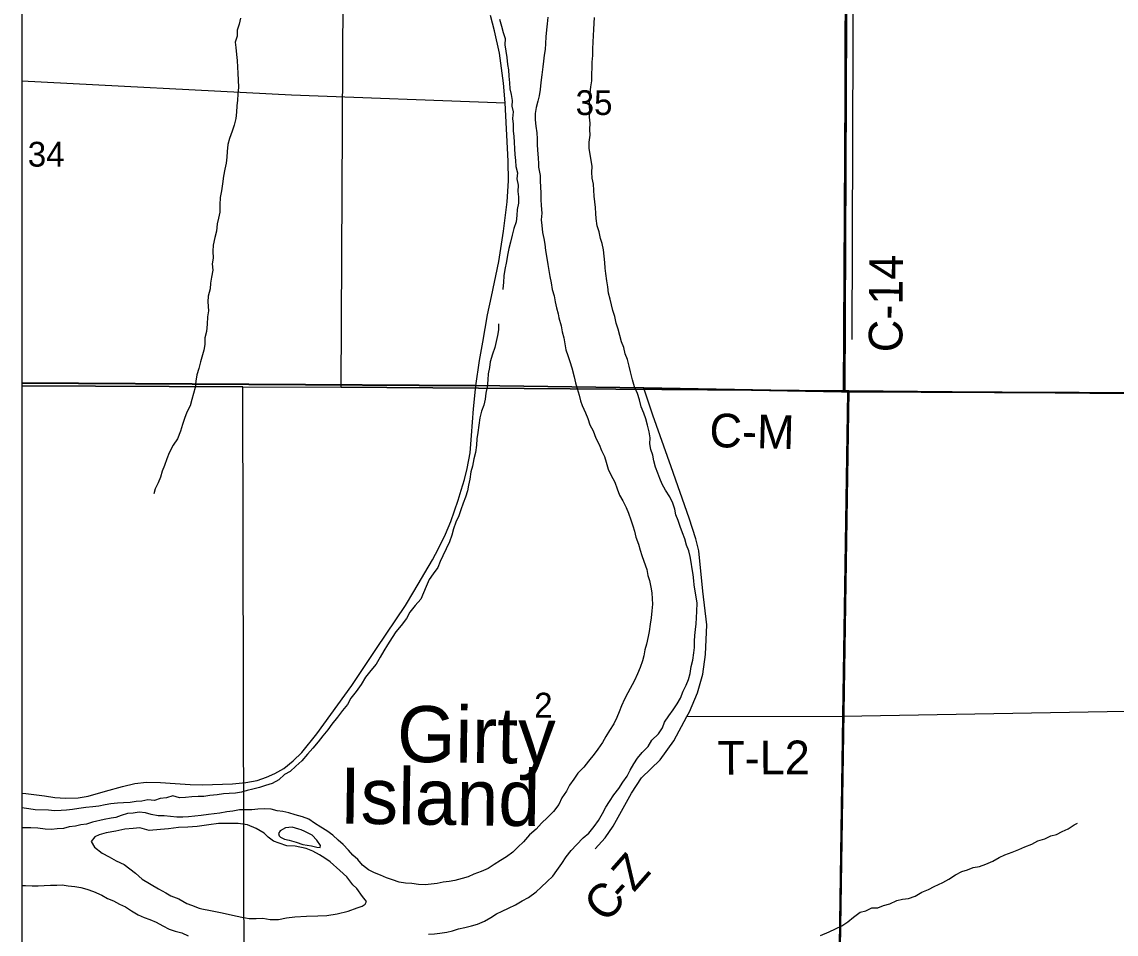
# Model space of a CAD drawing. Extents: x -6.2 to 37.4, y 0.2 to 22.2.
# Drawn here: x 1.681 to 2.605, y 14.922 to 15.692 of the extents above; entities that cross this region are included whole.
import ezdxf

# ---------------------------------------------------------------- set-up
doc = ezdxf.new("R2010")
doc.units = 0
for name, color, linetype in [('GM_X_County_Road', 7, 'Continuous'), ('GM_X_County_Road_Text', 7, 'Continuous'), ('GM_X_Major_River', 7, 'Continuous'), ('GM_X_Major_River_Text', 7, 'Continuous'), ('GM_X_Minor_River', 7, 'Continuous'), ('GM_X_Rail_Line', 7, 'Continuous'), ('GM_X_Section', 7, 'Continuous'), ('GM_X_Section_Text', 7, 'Continuous'), ('GM_X_Township_Road', 7, 'Continuous'), ('GM_X_Township_Road_Text', 7, 'Continuous'), ('GM_X_US_Shield', 7, 'Continuous'), ('SH_Cut_Line', 7, 'Continuous'), ('SH_Data', 7, 'Continuous')]:
    doc.layers.add(name, color=color, linetype=linetype)

msp = doc.modelspace()

# ---------------------------------------------------------------- linework, layer by layer
at = {"layer": 'GM_X_County_Road'}
for p, q in [((2.2059, 15.38289), (2.37282, 15.37973)), ((2.37282, 15.37973), (2.3744, 15.3797)), ((2.3744, 15.3797), (2.37821, 15.37963)), ((2.37821, 15.37963), (2.76889, 15.37789))]:
    msp.add_line(p, q, dxfattribs=at)
for points in [[(2.3744, 15.3797), (2.37573, 15.63221), (2.37619, 15.75431), (2.37666, 15.88116), (2.38391, 16.32379), (2.3895, 16.61161)], [(1.68086, 15.04078), (1.68433, 15.0405), (1.69989, 15.03854), (1.70873, 15.03727), (1.71756, 15.03678), (1.72844, 15.0371), (1.73669, 15.03833), (1.75134, 15.04253), (1.76581, 15.04659), (1.77609, 15.04898), (1.78597, 15.0501), (1.79782, 15.04996), (1.81015, 15.04919), (1.82283, 15.04814), (1.83322, 15.04786), (1.85852, 15.0487), (1.86995, 15.04982), (1.87941, 15.05157), (1.88726, 15.05439), (1.8945, 15.05762), (1.90191, 15.06174), (1.90983, 15.06812), (1.91705, 15.07513), (1.92981, 15.09111), (1.95939, 15.13183), (1.98024, 15.16291), (2.00467, 15.19926), (2.01184, 15.21123), (2.02751, 15.23774), (2.0325, 15.24735), (2.03853, 15.25941), (2.04301, 15.2702), (2.04918, 15.28815), (2.05177, 15.29663), (2.05451, 15.30567), (2.05689, 15.31506), (2.0592, 15.32824), (2.06054, 15.34275), (2.06209, 15.36536), (2.0642, 15.38463), (2.06723, 15.40608), (2.06989, 15.4217), (2.07399, 15.44463), (2.07722, 15.46006), (2.08349, 15.48957), (2.08756, 15.51522), (2.09061, 15.54017), (2.09162, 15.5578), (2.09134, 15.57428), (2.08889, 15.62362), (2.08742, 15.64013), (2.08395, 15.66565), (2.07985, 15.68454), (2.07645, 15.69747)], [(2.24231, 15.10557), (2.24455, 15.10965), (2.25109, 15.12557), (2.25574, 15.1415), (2.25791, 15.15782), (2.259, 15.18307), (2.25573, 15.21138), (2.2523, 15.24557), (2.24988, 15.25546), (2.24408, 15.27295), (2.22892, 15.31632), (2.21338, 15.35988), (2.2059, 15.38289)], [(2.37011, 14.85446), (2.37392, 15.10601), (2.37821, 15.37963)], [(2.16484, 14.99391), (2.16494, 14.99402), (2.1733, 15.00327), (2.18001, 15.01311), (2.19535, 15.04095), (2.20397, 15.05382), (2.21982, 15.06913), (2.23112, 15.08522), (2.24231, 15.10557)]]:
    msp.add_lwpolyline(points, dxfattribs=at)
at = {"layer": 'GM_X_Major_River'}
for p, q in [((1.91663, 15.00983), (1.91456, 15.01062)), ((1.80236, 14.95691), (1.80668, 14.95438))]:
    msp.add_line(p, q, dxfattribs=at)
for points in [[(2.12491, 15.69584), (2.12443, 15.69034), (2.12378, 15.68522), (2.1233, 15.67935), (2.12283, 15.67385), (2.12255, 15.66873), (2.12172, 15.66388), (2.12106, 15.65888), (2.12059, 15.65395), (2.11972, 15.64732), (2.11904, 15.64088)], [(2.17228, 15.4943), (2.17179, 15.49943), (2.17068, 15.50494), (2.16931, 15.50915), (2.16808, 15.51486), (2.16664, 15.51982), (2.16575, 15.526), (2.16531, 15.53028), (2.16501, 15.53522), (2.16452, 15.53997), (2.16404, 15.54491), (2.16356, 15.55005), (2.16345, 15.55498), (2.1624, 15.56012), (2.16211, 15.56506), (2.16219, 15.57), (2.16152, 15.57513), (2.16066, 15.58008), (2.1598, 15.58541), (2.15989, 15.59053), (2.16056, 15.59641), (2.16045, 15.60115), (2.16073, 15.60646), (2.16005, 15.61141), (2.16033, 15.61634), (2.16003, 15.62128), (2.15993, 15.62622), (2.16059, 15.63171), (2.16125, 15.63701), (2.1619, 15.64213), (2.162, 15.64801), (2.16228, 15.65313), (2.16218, 15.65807), (2.16284, 15.66356), (2.16293, 15.66926), (2.16322, 15.67495), (2.16331, 15.68045), (2.16378, 15.68557), (2.16406, 15.69088), (2.16414, 15.69562)], [(2.11904, 15.64088), (2.11837, 15.63501), (2.11752, 15.62951), (2.1164, 15.62497), (2.11508, 15.61968), (2.11424, 15.61457), (2.11428, 15.60925), (2.11481, 15.60393), (2.11548, 15.59842), (2.11577, 15.59329), (2.11595, 15.58835), (2.11617, 15.58375), (2.11663, 15.57733), (2.11693, 15.5722), (2.11703, 15.56932), (2.11827, 15.56231), (2.11838, 15.55718), (2.11865, 15.55307), (2.11896, 15.54711), (2.11906, 15.54199), (2.11936, 15.53705), (2.11982, 15.53059), (2.11934, 15.5249), (2.11983, 15.51996), (2.1203, 15.51426), (2.12135, 15.50912), (2.12221, 15.50436), (2.12288, 15.49903), (2.1241, 15.49256), (2.12477, 15.48724), (2.12563, 15.4821), (2.12649, 15.47715), (2.12772, 15.47182), (2.12858, 15.46611), (2.13019, 15.46077), (2.13105, 15.45563), (2.13229, 15.45049), (2.13372, 15.44553), (2.13422, 15.44211), (2.13601, 15.43544), (2.13687, 15.4303), (2.1383, 15.42515), (2.14003, 15.41526), (2.14165, 15.41049), (2.14346, 15.40515), (2.14507, 15.39981), (2.14703, 15.39238), (2.14827, 15.38742), (2.14971, 15.38247), (2.15132, 15.37694), (2.15238, 15.37218), (2.15384, 15.36803), (2.15656, 15.36205), (2.15875, 15.35708), (2.16037, 15.35193), (2.16313, 15.34677), (2.16549, 15.34066), (2.16824, 15.3353), (2.17024, 15.33015), (2.17263, 15.32501), (2.17424, 15.32041), (2.17584, 15.3145), (2.17804, 15.30972), (2.18141, 15.30353), (2.18352, 15.29787), (2.18533, 15.29253), (2.18828, 15.28774), (2.19102, 15.282), (2.19303, 15.27723), (2.19502, 15.27169), (2.19666, 15.2665), (2.19788, 15.26197), (2.19913, 15.25702), (2.2013, 15.2511), (2.20273, 15.24595), (2.20411, 15.24154), (2.20593, 15.23684), (2.20833, 15.22973), (2.20938, 15.22459), (2.21075, 15.22049), (2.21186, 15.21469), (2.21254, 15.20993), (2.21306, 15.20504), (2.21314, 15.20043), (2.21266, 15.19494), (2.21218, 15.18887), (2.21133, 15.18357), (2.21028, 15.17751), (2.20966, 15.17329), (2.2082, 15.16672), (2.20679, 15.16181), (2.20595, 15.15689), (2.20486, 15.15254), (2.20278, 15.14704), (2.20057, 15.1416), (2.19801, 15.13613), (2.19252, 15.12559), (2.18959, 15.12013), (2.18703, 15.11466), (2.18505, 15.10957), (2.18307, 15.10466)], [(2.13233, 14.97562), (2.1366, 14.98163), (2.1403, 14.98707), (2.14456, 14.99251), (2.14901, 14.99738), (2.1546, 15.00318), (2.15941, 15.00728), (2.16387, 15.01291), (2.16755, 15.01779), (2.17088, 15.02381), (2.17381, 15.02908), (2.17693, 15.03396), (2.18062, 15.03941), (2.1847, 15.04485), (2.1882, 15.0503), (2.1917, 15.05519), (2.19425, 15.06046), (2.19737, 15.06554), (2.20068, 15.07042), (2.20455, 15.0753), (2.20957, 15.08035), (2.21269, 15.08561), (2.21828, 15.09103), (2.22159, 15.09592), (2.22338, 15.10083), (2.22688, 15.10628), (2.23076, 15.11115), (2.23407, 15.11622), (2.2368, 15.12112), (2.23918, 15.12697), (2.24173, 15.13205), (2.24352, 15.13696), (2.24493, 15.14187), (2.24579, 15.14793), (2.2474, 15.15322), (2.24805, 15.15931), (2.24853, 15.16383), (2.24868, 15.16914), (2.24908, 15.17388), (2.24955, 15.17919), (2.24995, 15.1839), (2.25028, 15.18886), (2.25076, 15.19455), (2.25096, 15.20116), (2.24999, 15.20651), (2.24935, 15.21153), (2.24849, 15.21666), (2.24806, 15.22019), (2.2475, 15.22553), (2.24677, 15.23024), (2.24577, 15.23581), (2.24491, 15.24076), (2.24386, 15.24552), (2.24204, 15.25029), (2.24043, 15.25563), (2.23862, 15.26059), (2.23643, 15.26594), (2.235, 15.27109), (2.233, 15.27586), (2.23194, 15.28062), (2.23033, 15.28577), (2.22776, 15.29094), (2.22407, 15.29669), (2.22131, 15.30166), (2.21931, 15.30644), (2.21785, 15.31104), (2.21568, 15.31617), (2.21425, 15.32132), (2.21339, 15.32627), (2.21176, 15.33104), (2.21109, 15.33579), (2.21117, 15.34092), (2.21031, 15.34605), (2.20889, 15.35158), (2.20766, 15.35691), (2.20584, 15.36169), (2.20366, 15.36703), (2.20224, 15.37294), (2.20044, 15.37828), (2.19788, 15.38401), (2.19646, 15.38973), (2.19468, 15.39659), (2.19344, 15.40135), (2.19202, 15.40688), (2.1902, 15.41184), (2.18897, 15.41699), (2.18715, 15.42195), (2.18554, 15.4271), (2.1843, 15.43262), (2.1825, 15.43777), (2.18147, 15.44321), (2.17983, 15.44825), (2.17859, 15.45321), (2.17734, 15.45797), (2.1761, 15.46292), (2.17543, 15.46825), (2.17476, 15.47338), (2.17375, 15.47945), (2.17324, 15.48404), (2.17294, 15.48898), (2.17228, 15.4943)], [(2.18307, 15.10466), (2.1807, 15.09938), (2.17701, 15.09394), (2.17388, 15.08867), (2.17095, 15.08359), (2.16707, 15.07795), (2.16398, 15.07373), (2.15931, 15.06801), (2.15525, 15.06295), (2.1503, 15.05779), (2.14673, 15.05264), (2.14323, 15.04757), (2.14049, 15.04268), (2.13679, 15.03685), (2.13423, 15.03139), (2.12958, 15.02538), (2.12457, 15.02033), (2.11956, 15.01567), (2.11492, 15.01061), (2.10934, 15.00576), (2.10431, 14.99996), (2.09967, 14.99533), (2.09525, 14.99117), (2.09006, 14.9873), (2.0849, 14.98412), (2.07953, 14.98078), (2.07436, 14.97745), (2.06863, 14.97488), (2.06252, 14.9725), (2.05755, 14.9703), (2.05241, 14.96886), (2.04632, 14.96725), (2.04156, 14.96637), (2.03662, 14.96568), (2.03149, 14.96462), (2.02631, 14.96401), (2.02142, 14.96345), (2.01574, 14.96391), (2.01007, 14.96457), (2.00457, 14.96484), (1.99947, 14.96568), (1.99382, 14.96785), (1.98873, 14.96945), (1.98346, 14.97162), (1.97857, 14.97378), (1.97349, 14.97632), (1.96844, 14.98), (1.96454, 14.985), (1.96029, 14.9885), (1.95652, 14.99271), (1.95206, 14.99752), (1.94798, 15.00132), (1.94328, 15.00544), (1.93842, 15.00912), (1.93316, 15.01223), (1.92791, 15.01554), (1.92307, 15.01883), (1.91777, 15.02101), (1.91154, 15.02262), (1.90626, 15.02422), (1.90116, 15.02543), (1.89624, 15.02589), (1.89134, 15.02729), (1.88547, 15.02757), (1.87996, 15.02727), (1.87503, 15.02697), (1.86953, 15.02686), (1.8646, 15.02675), (1.85908, 15.02569), (1.85377, 15.02502), (1.84806, 15.02415), (1.84331, 15.02347), (1.83838, 15.02297), (1.83229, 15.02212), (1.82698, 15.02144), (1.82151, 15.0209), (1.81673, 15.02065), (1.8118, 15.02072), (1.80631, 15.02118), (1.80101, 15.02183), (1.7959, 15.02191), (1.79003, 15.02276), (1.78513, 15.02435), (1.77983, 15.02481), (1.77489, 15.02413), (1.77015, 15.02382), (1.76475, 15.02204), (1.76004, 15.02037), (1.7562, 15.01969), (1.75035, 15.01881), (1.74045, 15.0163), (1.73549, 15.01486), (1.73074, 15.01417), (1.72599, 15.01311), (1.72067, 15.01243), (1.7159, 15.01098), (1.71066, 15.01068), (1.70584, 15.01019), (1.70054, 15.01065), (1.6943, 15.01131), (1.68843, 15.01178)], [(1.68843, 15.01178), (1.68351, 15.01152), (1.68086, 15.01174)], [(1.80668, 14.95438), (1.81346, 14.95162), (1.82003, 14.94791), (1.82398, 14.94633), (1.83057, 14.94377), (1.83284, 14.94316), (1.84021, 14.94191), (1.84984, 14.93987), (1.85853, 14.93784), (1.86646, 14.9362), (1.8727, 14.93497), (1.87857, 14.93507), (1.88427, 14.93536), (1.8905, 14.93431), (1.89752, 14.9344), (1.90437, 14.93581), (1.91139, 14.93665), (1.92126, 14.93707), (1.93074, 14.9375), (1.93833, 14.93776), (1.94688, 14.93896), (1.9564, 14.94128), (1.96403, 14.9442), (1.96804, 14.94566), (1.97072, 14.94714), (1.9717, 14.9494), (1.96837, 14.95382), (1.96355, 14.96053), (1.96038, 14.96362), (1.95519, 14.97015), (1.94922, 14.97574), (1.94119, 14.98308), (1.9367, 14.98618), (1.932, 14.98891), (1.92656, 14.99184), (1.92072, 14.9942), (1.91146, 14.99605), (1.90465, 14.99654), (1.89805, 14.99872), (1.89334, 15.0005), (1.88885, 15.0038), (1.88531, 15.00727), (1.87874, 15.01097), (1.8714, 15.01431), (1.86346, 15.01538), (1.85625, 15.0153), (1.84677, 15.01525), (1.83861, 15.01424), (1.82872, 15.01287), (1.82094, 15.01223), (1.81317, 15.01197), (1.80461, 15.01077), (1.79797, 15.01011), (1.78829, 15.0095), (1.78056, 15.01171), (1.77467, 15.01104), (1.76765, 15.01057), (1.76022, 15.00879), (1.75205, 15.0074), (1.74614, 15.00578), (1.74251, 15.00413), (1.73941, 15), (1.74217, 14.99521), (1.74872, 14.99037), (1.75454, 14.98705), (1.76036, 14.98374), (1.76732, 14.98059), (1.77686, 14.97324), (1.78247, 14.96841), (1.79617, 14.96023), (1.80236, 14.95691)], [(1.91456, 15.01062), (1.9089, 15.01222), (1.90339, 15.01174), (1.8988, 15.00915), (1.89762, 15.00689), (1.89797, 15.00499), (1.89909, 15.00383), (1.90247, 15.00207), (1.90644, 15.00125), (1.91247, 14.99945), (1.91793, 14.99747), (1.92531, 14.99641), (1.92984, 14.9952), (1.93268, 14.99516), (1.9329, 14.99686), (1.92994, 15.00127), (1.92584, 15.00551), (1.91983, 15.00864), (1.91663, 15.00983)], [(2.02412, 14.92185), (2.02922, 14.92222), (2.0338, 14.92284), (2.0395, 14.9237), (2.04429, 14.9248), (2.04952, 14.9263), (2.05473, 14.92745), (2.06043, 14.92887), (2.06559, 14.93033), (2.07151, 14.93289), (2.07668, 14.93585), (2.08147, 14.93919), (2.08644, 14.9414), (2.0916, 14.94378), (2.09752, 14.94654), (2.10327, 14.95006), (2.10844, 14.95283), (2.11509, 14.95761), (2.11925, 14.96146), (2.12421, 14.96625), (2.12902, 14.97073), (2.13233, 14.97562)], [(1.68086, 14.963), (1.68399, 14.96308), (1.68968, 14.9628), (1.6946, 14.96272), (1.69973, 14.96303), (1.70504, 14.96333), (1.71026, 14.96322), (1.7149, 14.96355), (1.71988, 14.9628), (1.72568, 14.96206), (1.73059, 14.96123), (1.73569, 14.95982), (1.74134, 14.95803), (1.7483, 14.95488), (1.75318, 14.95196), (1.75827, 14.94999), (1.76315, 14.94726), (1.76842, 14.94509), (1.77348, 14.9416), (1.7791, 14.9381), (1.784, 14.93593), (1.7889, 14.93434), (1.79435, 14.93198), (1.7998, 14.92886), (1.80525, 14.92612), (1.81015, 14.92453), (1.81581, 14.92293), (1.82127, 14.92057)]]:
    msp.add_lwpolyline(points, dxfattribs=at)
at = {"layer": 'GM_X_Minor_River'}
for points in [[(2.27558, 15.76113), (2.38269, 15.7616), (2.38148, 15.42375)], [(1.86539, 15.69521), (1.86416, 15.68992), (1.86256, 15.685), (1.86248, 15.67988), (1.86088, 15.67497), (1.86155, 15.67021), (1.86202, 15.66432), (1.86251, 15.65938), (1.86298, 15.65368), (1.86327, 15.64874), (1.86355, 15.64266), (1.86383, 15.63677), (1.86316, 15.6309), (1.86288, 15.62597), (1.86242, 15.62104), (1.86214, 15.61573), (1.86148, 15.61043), (1.86006, 15.60475), (1.85827, 15.59965), (1.85626, 15.59342), (1.85485, 15.58851), (1.85418, 15.58263), (1.85391, 15.5777), (1.85326, 15.57278), (1.85222, 15.56767), (1.85099, 15.5618), (1.85012, 15.55536), (1.84926, 15.54949), (1.84822, 15.54381), (1.84792, 15.53755), (1.84801, 15.53148), (1.84697, 15.52637), (1.84575, 15.52145), (1.84527, 15.51539), (1.84385, 15.51009), (1.84222, 15.50348), (1.84213, 15.49835), (1.84241, 15.49265), (1.84138, 15.48774), (1.84205, 15.48241), (1.84081, 15.47635), (1.84016, 15.47143), (1.83988, 15.4665), (1.83807, 15.46045), (1.8378, 15.45571), (1.83843, 15.44792), (1.83759, 15.443), (1.83729, 15.43693), (1.83662, 15.43068), (1.83539, 15.42538), (1.83529, 15.41969), (1.83445, 15.41477), (1.83163, 15.40494), (1.83021, 15.39945), (1.8286, 15.39398)], [(2.08394, 15.69437), (2.08573, 15.68846), (2.08716, 15.68293), (2.08897, 15.67797), (2.08849, 15.67247), (2.09021, 15.66182), (2.09087, 15.65611), (2.09155, 15.65136), (2.09184, 15.64623), (2.0925, 15.64052), (2.09279, 15.63539), (2.09404, 15.63063), (2.09471, 15.62568)], [(2.09471, 15.62568), (2.09444, 15.62094), (2.09568, 15.61599), (2.09502, 15.61031), (2.0955, 15.60555), (2.0956, 15.60005), (2.09628, 15.59529), (2.09657, 15.59054), (2.09667, 15.58484), (2.09696, 15.57991), (2.09745, 15.57496), (2.09774, 15.57002), (2.09917, 15.56469), (2.0987, 15.55938), (2.09993, 15.55405), (2.09966, 15.54893), (2.10015, 15.54417), (2.10006, 15.53905), (2.09883, 15.53356), (2.09855, 15.52844), (2.09808, 15.52314), (2.09609, 15.51766), (2.09467, 15.51199), (2.09324, 15.50594), (2.09201, 15.50064), (2.09078, 15.49496), (2.08993, 15.48966), (2.08867, 15.48285), (2.08783, 15.47774), (2.08735, 15.47205), (2.08688, 15.46674), (2.08683, 15.46619)], [(2.0831, 15.43718), (2.08315, 15.43681), (2.08326, 15.43206), (2.08242, 15.42714), (2.0812, 15.42222), (2.08016, 15.41711), (2.07817, 15.41145), (2.07616, 15.40503), (2.07551, 15.4001), (2.07447, 15.3948), (2.0742, 15.38968), (2.07353, 15.384), (2.07249, 15.37851), (2.07183, 15.3734), (2.0708, 15.36848), (2.06882, 15.36338), (2.06759, 15.35771), (2.06672, 15.35146), (2.06567, 15.3454), (2.06501, 15.34009), (2.06473, 15.33459), (2.06368, 15.32854), (2.06225, 15.32305), (2.0612, 15.31699), (2.05979, 15.31208), (2.05893, 15.30602), (2.0579, 15.30091), (2.05706, 15.29599), (2.05545, 15.2907), (2.05347, 15.28579), (2.05147, 15.27994), (2.04968, 15.27503), (2.04713, 15.26957), (2.04532, 15.2639), (2.04372, 15.2588), (2.04172, 15.25295), (2.03916, 15.24729), (2.03622, 15.24126), (2.03386, 15.23636), (2.03188, 15.23146), (2.02818, 15.22601), (2.02469, 15.22113), (2.02213, 15.21547), (2.01976, 15.21001), (2.01758, 15.20454), (2.01294, 15.19929), (2.00849, 15.19367), (2.00555, 15.1884), (2.00109, 15.18239), (1.99664, 15.17714), (1.99353, 15.17226), (1.98963, 15.16605), (1.98651, 15.16117), (1.98339, 15.15571), (1.97987, 15.14988), (1.97542, 15.14444), (1.97097, 15.13882), (1.96726, 15.13261), (1.96299, 15.12679), (1.95853, 15.12097), (1.9556, 15.11589), (1.95153, 15.11064), (1.94726, 15.1052), (1.94261, 15.0992), (1.93912, 15.09432), (1.93486, 15.08926), (1.93098, 15.08419)], [(1.8286, 15.39398), (1.82775, 15.38867), (1.82728, 15.38337), (1.82568, 15.37827), (1.82446, 15.37316), (1.82304, 15.36787), (1.8201, 15.3626), (1.81812, 15.35712), (1.81651, 15.35202), (1.8149, 15.34635), (1.81233, 15.34013), (1.80844, 15.33468), (1.8053, 15.32828), (1.80332, 15.32299), (1.80114, 15.31752), (1.79935, 15.31261), (1.79794, 15.3077), (1.79596, 15.3028), (1.79341, 15.2979), (1.79239, 15.29355)], [(1.93098, 15.08419), (1.92634, 15.07895), (1.92208, 15.0737), (1.91706, 15.06827), (1.91224, 15.0636), (1.90743, 15.05931), (1.90264, 15.05654), (1.89764, 15.05225), (1.89228, 15.0491), (1.88656, 15.04748), (1.88141, 15.04566), (1.8759, 15.04442), (1.87114, 15.04316), (1.86618, 15.04172), (1.86124, 15.04103), (1.85593, 15.04074), (1.85099, 15.04024), (1.84567, 15.03956), (1.8396, 15.0389), (1.83447, 15.03821), (1.82973, 15.0381), (1.82441, 15.0378), (1.81891, 15.03731), (1.81378, 15.03701), (1.80831, 15.03861), (1.80298, 15.03699), (1.79766, 15.0365), (1.7927, 15.03467), (1.78721, 15.03514), (1.78208, 15.03408), (1.77733, 15.03377), (1.7722, 15.03309), (1.7667, 15.03279), (1.76158, 15.03249), (1.75607, 15.032), (1.75112, 15.03094), (1.7458, 15.02988), (1.74086, 15.02939), (1.73478, 15.02872), (1.7289, 15.02805), (1.72357, 15.02719), (1.71863, 15.0265), (1.71389, 15.0262), (1.70839, 15.02609), (1.70328, 15.02655), (1.6921, 15.02672), (1.68681, 15.02775), (1.68095, 15.02859), (1.68086, 15.02861)], [(2.44615, 14.95966), (2.45094, 14.96225), (2.45819, 14.96536), (2.46336, 14.96832), (2.46892, 14.97184), (2.47447, 14.9748), (2.47923, 14.97624), (2.484, 14.97826), (2.48914, 14.97913), (2.49448, 14.98094), (2.50059, 14.98351), (2.50576, 14.98647), (2.51072, 14.98886), (2.51683, 14.99123), (2.52256, 14.99343), (2.52752, 14.99563), (2.53344, 14.99781), (2.53841, 15.00059), (2.54432, 15.00239), (2.54948, 15.00478), (2.55424, 15.00604), (2.55902, 15.00862), (2.56418, 15.01082), (2.56916, 15.01417), (2.57203, 15.01545)], [(2.35507, 14.92081), (2.36233, 14.92393), (2.36768, 14.9265), (2.37303, 14.92889), (2.37802, 14.93242), (2.38301, 14.93614), (2.38858, 14.94042), (2.39334, 14.94167), (2.3985, 14.94406), (2.40343, 14.94418), (2.4082, 14.946), (2.41353, 14.94763), (2.41946, 14.95039), (2.4244, 14.95145), (2.42934, 14.95195), (2.43487, 14.95395), (2.44062, 14.95747), (2.44615, 14.95966)]]:
    msp.add_lwpolyline(points, dxfattribs=at)
at = {"layer": 'GM_X_Rail_Line'}
msp.add_lwpolyline([(1.68086, 18.39138), (1.68086, 15.3872), (2.06408, 15.38491), (2.20578, 15.38316), (2.37429, 15.37998), (2.37809, 15.37991), (2.76877, 15.37817), (2.87203, 15.37415), (2.88287, 15.8796)], dxfattribs=at)
msp.add_lwpolyline([(1.68086, 15.3872), (1.68086, 14.30742), (2.87188, 14.30742), (2.87214, 14.35429), (2.87246, 14.85833), (2.87203, 15.37415), (2.76877, 15.37817), (2.37809, 15.37991), (2.37429, 15.37998), (2.20578, 15.38316), (2.06408, 15.38491)], close=True, dxfattribs=at)
at = {"layer": 'GM_X_Section'}
for points in [[(2.37779, 15.87968), (2.37562, 15.38046), (1.95052, 15.38351), (1.95281, 15.87951)], [(2.88344, 15.87997), (2.8728, 15.37579), (2.37903, 15.38039), (2.37562, 15.38046), (2.37779, 15.87968)], [(1.86735, 15.38393), (1.95052, 15.38351), (2.37562, 15.38046), (2.37903, 15.38039), (2.3709, 14.8559), (1.86851, 14.86987)], [(2.37903, 15.38039), (2.8728, 15.37579), (2.87069, 14.86011), (2.3709, 14.8559)]]:
    msp.add_lwpolyline(points, close=True, dxfattribs=at)
at = {"layer": 'GM_X_Township_Road'}
msp.add_line((1.68086, 15.38692), (2.0642, 15.38463), dxfattribs=at)
for points in [[(1.68086, 15.64223), (1.90851, 15.63035), (2.08889, 15.62362)], [(2.24231, 15.10557), (2.37392, 15.10601), (2.77238, 15.11306)]]:
    msp.add_lwpolyline(points, dxfattribs=at)
at = {"layer": 'GM_X_US_Shield'}
for points in [[(1.68086, 15.89387), (1.68086, 15.38487), (1.86735, 15.38393), (1.95052, 15.38351), (1.95281, 15.87951)], [(1.68086, 15.38487), (1.68086, 14.87109), (1.86851, 14.86987), (1.86735, 15.38393)]]:
    msp.add_lwpolyline(points, close=True, dxfattribs=at)
at = {"layer": 'SH_Cut_Line'}
msp.add_lwpolyline([(1.68086, 20.39726), (1.68086, 14.30742), (5.08086, 14.30742)], dxfattribs=at)
at = {"layer": 'SH_Data'}
msp.add_line((1.68086, 21.10742), (1.68086, 14.30742), dxfattribs=at)

# ---------------------------------------------------------------- texts
at = {"layer": 'GM_X_County_Road_Text'}
for s, height, rotation, p in [('C-14', 0.028409, 89.6571, (2.42413, 15.41301)), ('C-M', 0.028409, 358.53994, (2.26102, 15.33313)), ('Z', 0.02841, 48.60676, (2.19755, 14.95663)), ('C', 0.02841, 48.15059, (2.17404, 14.93037)), ('-', 0.02841, 48.18623, (2.18962, 14.94776))]:
    msp.add_text(s, height=height, rotation=rotation, dxfattribs=at).set_placement(p)
at = {"layer": 'GM_X_Major_River_Text'}
for s, rotation, p in [('Girty', 359.22923, (1.99734, 15.06738)), ('Island', 359.22882, (1.94898, 15.01529))]:
    msp.add_text(s, height=0.047376, rotation=rotation, dxfattribs=at).set_placement(p)
at = {"layer": 'GM_X_Section_Text'}
for s, height, p in [('35', 0.020928, (2.14832, 15.61333)), ('34', 0.020928, (1.68582, 15.56979)), ('2', 0.02093, (2.11332, 15.10474))]:
    msp.add_text(s, height=height, rotation=0.00001, dxfattribs=at).set_placement(p)
at = {"layer": 'GM_X_Township_Road_Text'}
msp.add_text('T-L2', height=0.028409, rotation=0.33488, dxfattribs=at).set_placement((2.26798, 15.0565))

doc.saveas('drawing.dxf')
